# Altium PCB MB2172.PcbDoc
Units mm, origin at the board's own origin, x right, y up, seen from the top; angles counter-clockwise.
Board outline 55.25 x 31 mm, 2 copper layers (Top Layer, Bottom Layer), stack 0.603 mm thick; 40 components, 47 nets, 182 pads, 844 vias.
Unrouted connection lines stored in the file: 99.
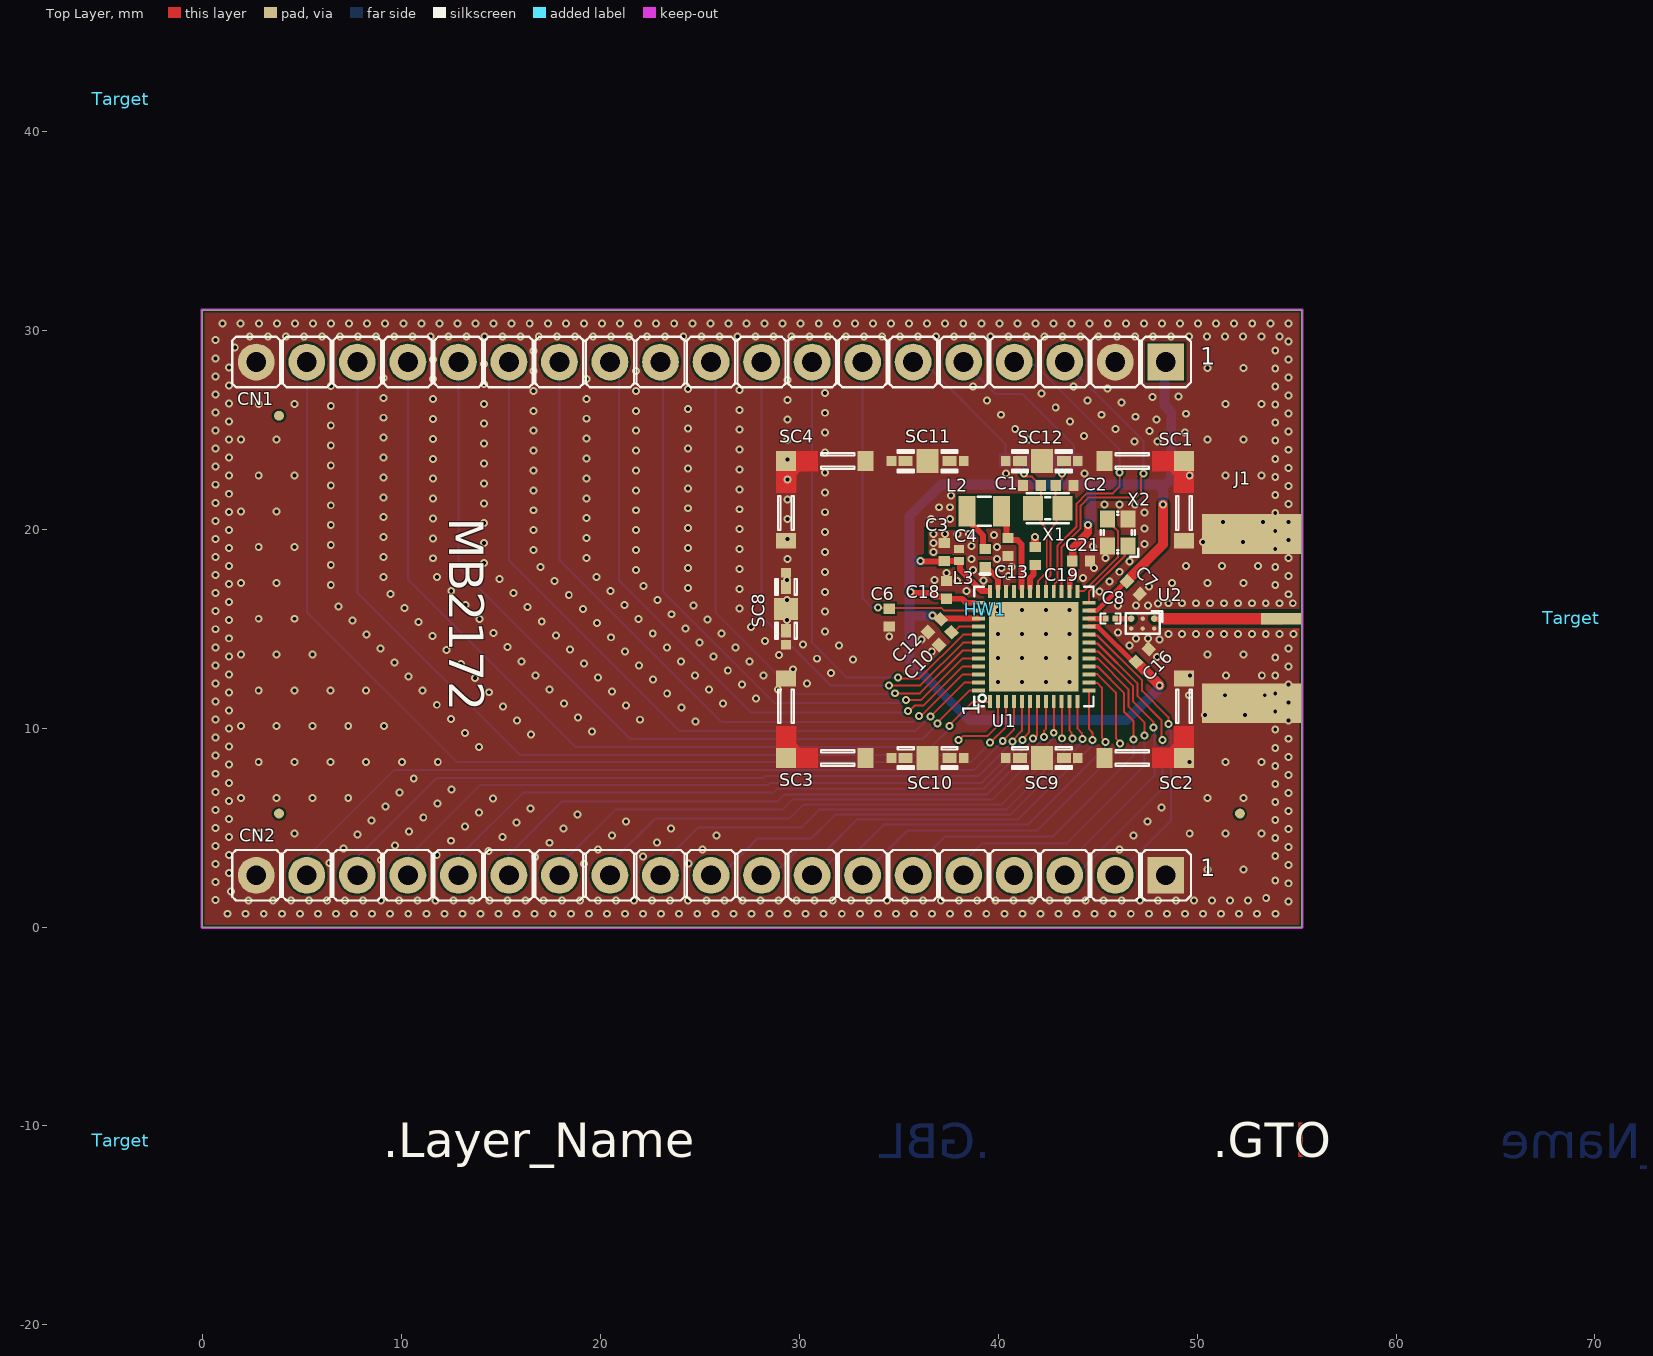
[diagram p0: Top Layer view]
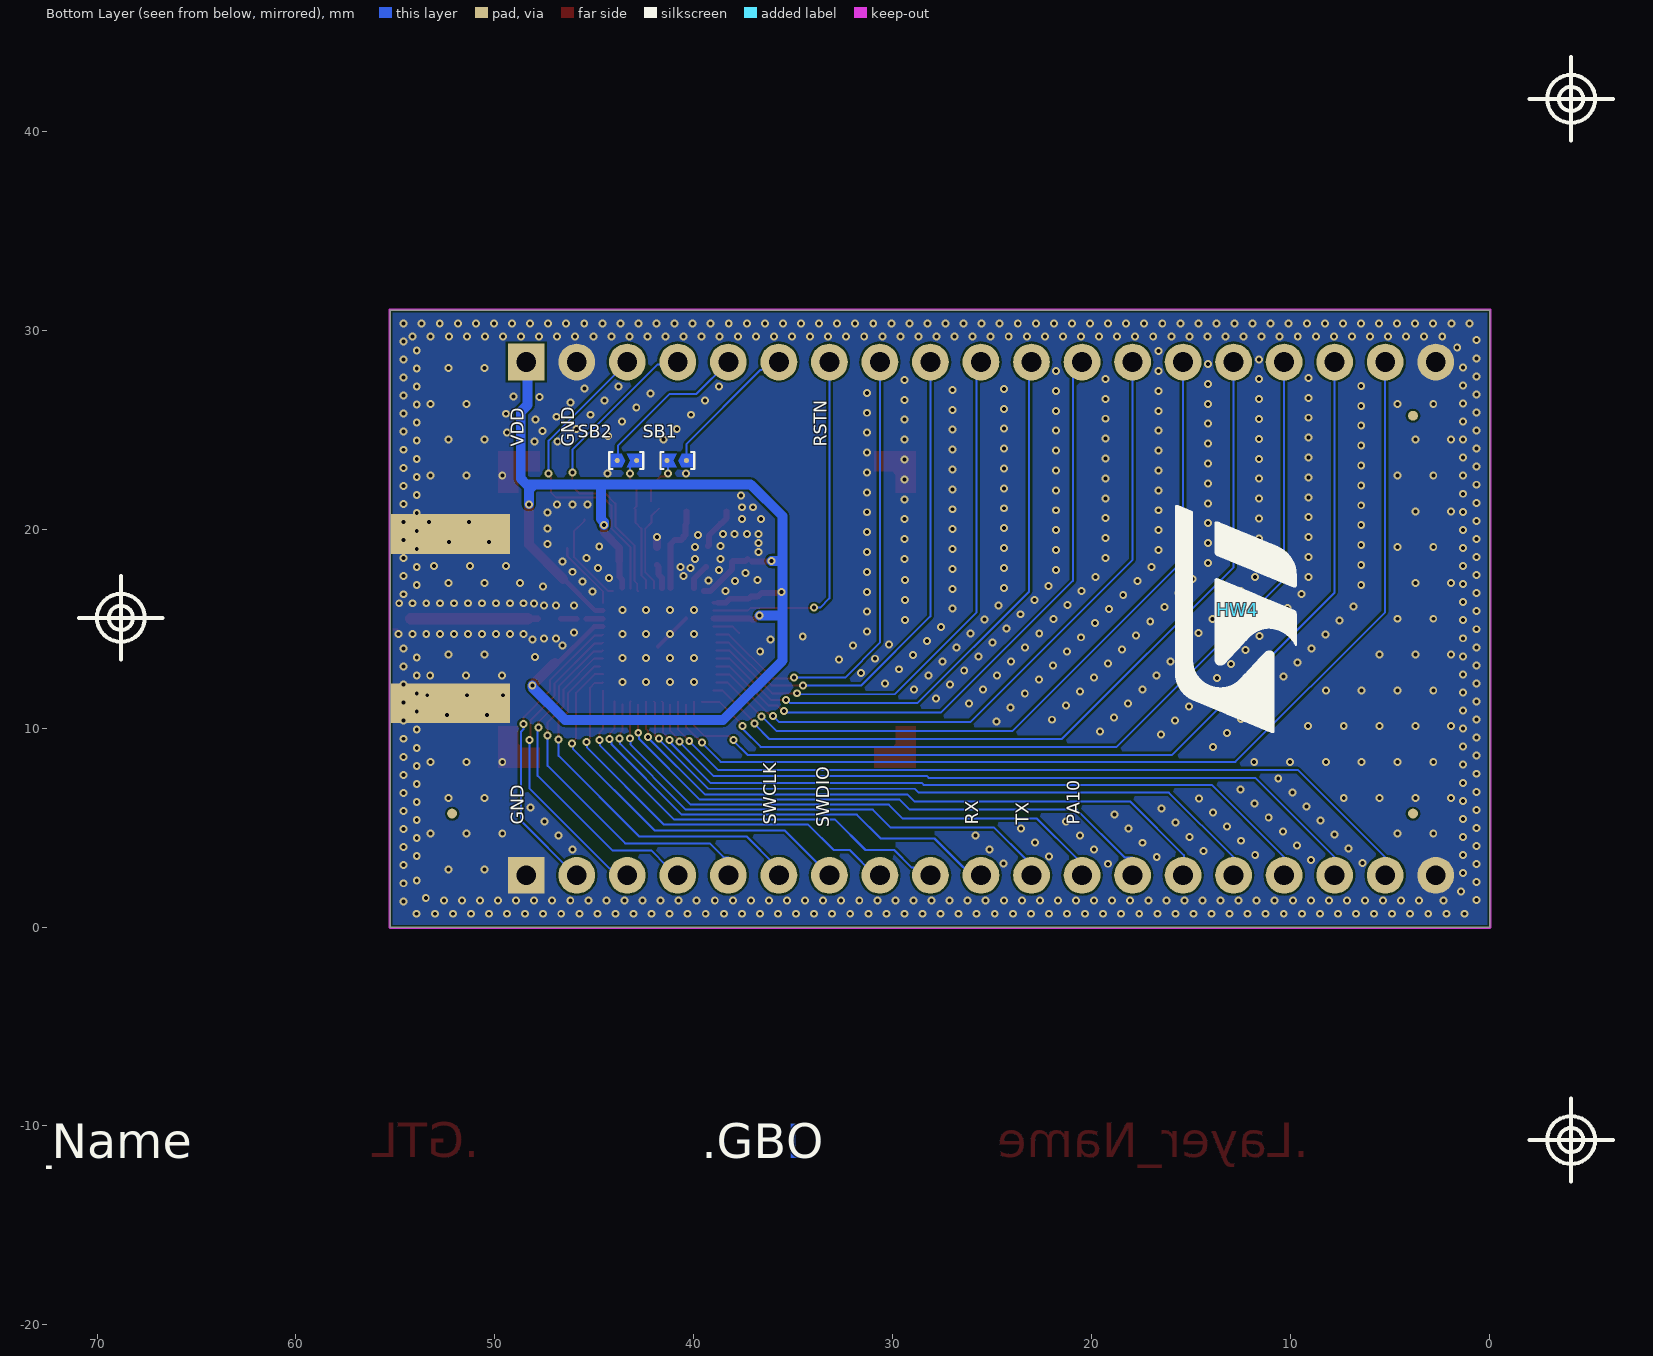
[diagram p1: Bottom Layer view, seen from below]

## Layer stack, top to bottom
Top Solder: solder mask 0.02, Solder Resist, Dk 3.5
Top Layer: signal copper 0.035
Dielectric 1: dielectric 0.533, TU-768 (3 x 7628), Dk 4.6
Bottom Layer: signal copper 0.035
Bottom Solder: solder mask 0.02, Solder Resist, Dk 3.5

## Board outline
0,0 55.25,0 55.25,31 0,31

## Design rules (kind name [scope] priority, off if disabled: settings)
Clearance Clearance_RF [InNet('NetJ1_1')] p1: gap=0.14 ignorepadtopadclearanceinfootprint=FALSE
Clearance [All] p2: gap=0.1 ignorepadtopadclearanceinfootprint=FALSE
HoleToHoleClearance [All] p1: gap=0.15 allowstackedmicrovias=TRUE
MinimumSolderMaskSliver [All] p1: minsoldermaskwidth=0
ParallelSegment [All] p1: limit=10 gap=0.3
PlaneClearance [All] p1: clearance=0
PlaneConnect [InNet('GND')] p1: planeconnectstyle=Direct reliefexpansion=0.508 reliefentries=4 reliefconductorwidth=0.254 reliefairgap=0.254
PolygonConnect [InNet('GND')] p1: connectstyle=Direct reliefconductorwidth=0.254 reliefentries=4 polygonreliefangle="90 Angle" airgapwidth=0.254
RoutingVias [All] p1: holewidth=0.2 width=0.4 viastyle="Through Hole" minholewidth=0.2 minwidth=0.4 maxholewidth=0.2 maxwidth=0.4
SilkToSilkClearance [All] p1: silktosilkclearance=0
SilkToSolderMaskClearance [IsPad] p1: minsilkscreentomaskgap=0 clearancetoexposedcopper=TRUE
SolderMaskExpansion [All] p1: expansion=0.102 istentingtop=FALSE
Width [All] p1: maxlimit=0.7 minlimit=0.1 preferedwidth=0.1
24 further rules are at their usual default settings.

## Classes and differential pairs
component class MB2172: C1 C2 C3 C4 C6 C7 C10 C12 C13 C16 C18 C19 C21 CN1 CN2 L2 L3 SB1 SB2 SC1 SC2 SC3 SC4 SC8 SC9 SC10 SC11 SC12 U1 U2 X1 X2

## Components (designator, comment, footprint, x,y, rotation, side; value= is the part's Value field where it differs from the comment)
C1 "Capacitor" C0402 41.691,22.2 r180 top value=10pF
C2 "Capacitor" C0402 43.341,22.2 r180 top value=10pF
C3 "Capacitor" C0402 37.291,18.85 r270 top value=4.7uF
C4 "Capacitor" C0201_H0P3 38.041,18.7 r270 top value=100nF
C6 "Capacitor" C0402 34.524,15.55 r270 top value=10nF
C7 "Capacitor" C0402 46.8,17.05 r135 top value=1uF
C8 "Capacitor" 20p_capacitor_SMD_0201 45.644,15.5 r90 top value=20pF
C10 "Capacitor" C0402 37.341,14.5 r225 top value=100nF
C12 "Capacitor" C0402 36.791,15.15 r45 top value=1uF
C13 "Capacitor" C0402 40.5,19.1 r90 top value=4.7uF
C16 "Capacitor" C0402 47.25,13.65 r225 top value=1uF
C18 "Capacitor" C0402 37.4,16.95 r270 top value=1uF
C19 "Capacitor" C0402 41.861,18.65 r270 top value=0.22uF
C21 "Capacitor" C0402 44.174,18.4 r180 top value=1uF
CN1 "Header 19x1" header_19x1 25.565,28.4 r180 top locked
CN2 "Header 19x1" header_19x1 25.565,2.6 r180 top locked
Designator16 "Comment" IMPEDANCE_TABLE 92.199,-23.657 r0 top
HW1 "S02-20150300" SHIELD_HARWIN_S02-20150300_15X20_H3 39.344,15.964 r90 top locked
HW4 "Logo" LOGO_ST 12.65,15.95 r90 bottom
J1 "SMA_connector" SMA_AMPHENOL_132415 54.225,15.5 r180 top
L2 "Inductor" IND_0805_MURATA_LQM21 39.299,20.9 r180 top value=10uH
L3 "Inductor" C0402 39.35,18.55 r270 top value=22nH
SB1 "SB_ON" SOLDER-BRIDGE_R0402-0R 40.823,23.45 r0 bottom value=0R
SB2 "SB_ON" SOLDER-BRIDGE_R0402-0R 43.4,23.45 r180 bottom value=0R
SC1 "Shield-clip_S0951-46R" CLIP_HARWIN_S0981-46R 49.337,23.418 r90 top value=S0981-46R
SC2 "Shield-clip_S0951-46R" CLIP_HARWIN_S0981-46R 49.337,8.5 r0 top value=S0981-46R
SC3 "Shield-clip_S0951-46R" CLIP_HARWIN_S0981-46R 29.337,8.5 r270 top locked value=S0981-46R
SC4 "Shield-clip_S0951-46R" CLIP_HARWIN_S0981-46R 29.337,23.418 r180 top value=S0981-46R
SC8 "Shield-clip_S0951-46R" CLIP_HARWIN_S0951-46R 29.337,15.993 r270 top value=S0951-46R
SC9 "Shield-clip_S0951-46R" CLIP_HARWIN_S0951-46R 42.198,8.5 r180 top value=S0951-46R
SC10 "Shield-clip_S0951-46R" CLIP_HARWIN_S0951-46R 36.448,8.5 r180 top value=S0951-46R
SC11 "Shield-clip_S0951-46R" CLIP_HARWIN_S0951-46R 36.448,23.418 r180 top value=S0951-46R
SC12 "Shield-clip_S0951-46R" CLIP_HARWIN_S0951-46R 42.198,23.418 r180 top value=S0951-46R
Target "" "Target PCB" -4.1,-10.71 r90 top
Target "" "Target PCB" 68.8,15.54 r90 top
Target "" "Target PCB" -4.1,41.628 r90 top
U1 "STM32WB07" ICC_QFN48-EPAD-4P5X4P5_6X6_P040 41.794,14.1 r90 top
U2 "MLPF-WB55-01E3" ICC_CSPG_6BUMPS_1X1P60_P050-P0577 47.265,15.25 r270 top value=MLPF-NRG-01D3
X1 "XTAL_2_PINS" CRY_NX2012SA_2P 42.491,21.05 r0 top value=32.768kHz
X2 "XTAL_4_PINS" CRY_NX2016SA_4P 46.011,19.831 r90 top value=32MHz

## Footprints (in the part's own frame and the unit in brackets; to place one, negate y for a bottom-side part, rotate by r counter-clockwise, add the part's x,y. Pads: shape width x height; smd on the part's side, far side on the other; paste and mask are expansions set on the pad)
20p_capacitor_SMD_0201 [mm] "SMD 0201"
  rect 0.3x0.28 smd mask+0.05: 1(0.002,0.238) 2(0.002,-0.232)
  silkscreen extent -0.25,-0.51 0.25,0.51, body extent -0.15,-0.3 0.15,0.3, height 0.3
C0201_H0P3 [mm] "MCD-00699"
  rect 0.4x0.5 smd mask+0.05: 1(-0.3,0) 2(0.3,0)
  body extent -0.32,-0.17 0.32,0.17, height 0.33
C0402 [mm]
  rect 0.51x0.56 smd mask+0.05: 1(-0.45,0) 2(0.45,0)
  body extent -0.5,-0.3 0.5,0.3, height 0.4
CLIP_HARWIN_S0951-46R [mm] "MCD-01587_CLIP-X1"
  rect 0.48x0.5 smd mask+0.1: 1(-1.81,0) 1(1.81,0)
  rect 0.7x0.5 smd mask+0.1: 1(-1.1,0) 1(1.1,0)
  rect 1.1x1.2 smd mask+0.1: 1(0,0)
  silkscreen extent -1.5,-0.55 1.5,0.55, body extent -2.05,-0.65 2.05,0.65, height 1.28
CLIP_HARWIN_S0981-46R [mm] "MCD-02164"
  rect 0.8x1 smd mask+0.05: 1(-4,0)
  rect 1x0.8 smd mask+0.05: 1(0,4)
  rect 1x1 smd mask+0.05: 1(0,0)
  Top Layer region: -1.6,-0.5 0.5,-0.5 0.5,1.6 -0.5,1.6 -0.5,0.7 -0.7,0.5 -1.6,0.5
  silkscreen extent -3.45,-0.4 0.4,3.45, body extent -4.3,-0.46 0.46,4.3, height 1.4
CRY_NX2012SA_2P [mm]
  rect 1x1.25 smd mask+0.05: 1(-0.75,0) 2(0.75,0)
  silkscreen extent -1.05,-0.75 1.05,0.75, body extent -1.05,-0.63 1.05,0.63, height 0.6
CRY_NX2016SA_4P [mm]
  rect 0.85x0.75 smd mask+0.05: 1(-0.675,-0.525) 2(0.675,-0.525) 3(0.675,0.525) 4(-0.675,0.525)
  silkscreen extent -1.22,-1.02 1.05,0.85, body extent -1.05,-0.85 1.05,0.85, height 0.7
header_19x1 [mm] "MCD-01897"
  rect 1.85x1.85 / inner round 1.85 / far side rect 1.85x1.85 hole 1 mask+0.05: 1(-22.86,0)
  round 1.85 hole 1 mask+0.05: 2(-20.32,0) 3(-17.78,0) 4(-15.24,0) 5(-12.7,0) 6(-10.16,0) 7(-7.62,0) 8(-5.08,0) 9(-2.54,0) 10(0,0) 11(2.54,0) 12(5.08,0) 13(7.62,0) 14(10.16,0) 15(12.7,0) 16(15.24,0) 17(17.78,0) 18(20.32,0) 19(22.86,0)
  silkscreen extent -24.13,-1.27 24.07,1.27, body extent -24.26,-1.27 21.59,1.27, height 8.38
ICC_CSPG_6BUMPS_1X1P60_P050-P0577 [mm] "MCD-03490"
  round 0.32 smd paste+0 mask+0: A1(-0.25,0.577) A3(-0.25,-0.577)
  round 0.22 smd paste+0 mask+0: A2(-0.25,0) B1(0.25,0.577) B2(0.25,0) B3(0.25,-0.577)
  silkscreen extent -0.64,-0.85 0.51,0.97, body extent -0.51,-0.81 0.51,0.81, height 0.7
ICC_QFN48-EPAD-4P5X4P5_6X6_P040 [mm] "MCD-03488"
  rect 0.65x0.2 smd mask+0.05: 1(-2.775,2.2) 2(-2.775,1.8) 3(-2.775,1.4) 4(-2.775,1) 5(-2.775,0.6) 6(-2.775,0.2) 7(-2.775,-0.2) 8(-2.775,-0.6) 9(-2.775,-1) 10(-2.775,-1.4) 11(-2.775,-1.8) 12(-2.775,-2.2) 25(2.775,-2.2) 26(2.775,-1.8) 27(2.775,-1.4) 28(2.775,-1) 29(2.775,-0.6) 30(2.775,-0.2) 31(2.775,0.2) 32(2.775,0.6) 33(2.775,1) 34(2.775,1.4) 35(2.775,1.8) 36(2.775,2.2)
  rect 0.2x0.65 smd mask+0.05: 13(-2.2,-2.775) 14(-1.8,-2.775) 15(-1.4,-2.775) 16(-1,-2.775) 17(-0.6,-2.775) 18(-0.2,-2.775) 19(0.2,-2.775) 20(0.6,-2.775) 21(1,-2.775) 22(1.4,-2.775) 23(1.8,-2.775) 24(2.2,-2.775) 37(2.2,2.775) 38(1.8,2.775) 39(1.4,2.775) 40(1,2.775) 41(0.6,2.775) 42(0.2,2.775) 43(-0.2,2.775) 44(-0.6,2.775) 45(-1,2.775) 46(-1.4,2.775) 47(-1.8,2.775) 48(-2.2,2.775)
  rect 4.5x4.5 smd mask+0.05: 49(0,0)
  silkscreen extent -3,-3 3,3, body extent -3,-3 3,3, height 0.91
IMPEDANCE_TABLE [mm]
IND_0805_MURATA_LQM21 [mm] "MCD-02317"
  rect 0.85x1.55 smd mask+0.05: 1(-0.875,0) 2(0.875,0)
  silkscreen extent -0.33,-0.72 0.33,0.72, body extent -1.1,-0.72 1.1,0.72, height 1.45
LOGO_ST [mm]
  silkscreen extent -6.18,-2.95 5.25,3.14
SHIELD_HARWIN_S02-20150300_15X20_H3 [mm] "MCD-03126"
  body extent -7.6,-10.1 7.6,10.1, height 3.25
SMA_AMPHENOL_132415 [mm]
  rect 2.05x0.58 smd mask+0: 1(0,0)
  rect 5x2 smd: 2(1.475,4.25) 2(1.475,-4.25)
  rect 6x2 smd far side: 2(1.975,4.25) 2(1.975,-4.25)
  body extent -10.55,-4.76 4.36,4.76, height 4.11
SOLDER-BRIDGE_R0402-0R [mil] "MCD-01619"
  round 10 smd paste-393.7: 1(-17.72,0) 2(20.67,0)
  Top Layer region: -30.51,-13.78 -30.51,13.78 -8.37,13.78 -1.48,0 -8.37,-13.78
  Top Layer region: 1.48,13.78 8.37,0 1.48,-13.78 30.51,-13.78 30.51,13.78
  silkscreen extent -33,-17 33,17, body extent -20,-12 20,12, height 14
"Target PCB" [mm] "TargetA"

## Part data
C1 C2: library part MCD-00015, "Capacitor, MLCC, 10pF, 50V, NPO, +/-5%, 0402, T=0.5mm", Manufacturer=YAGEO, Manufacturer_Part_Number=CC0402JRNPO9BN100, Package=0402
C3 C13: library part MCD-03431, "Capacitor, MLCC, 4.7uF, X5R, 10V, +/-20%, 0402, T=0.5mm", Manufacturer=MURATA, Manufacturer_Part_Number=GRM155R61A475MEAAD, Package=0402
C4: library part MCD-01535, "Capacitor, MLCC,100nF, 10V, X5R, +/-10%, 0201, T=0.3mm", Manufacturer=MURATA, Manufacturer_Part_Number=GRM033R61A104KE15, Package=0201
C6: library part MCD-00011, "Capacitor, MLCC, 10nF, 16V, X7R, +/-10%, 0402, T=0.5mm", Manufacturer=YAGEO, Manufacturer_Part_Number=CC0402KRX7R7BB103, Package=0402
C7 C12 C16 C18 C21: library part MCD-03432, "Capacitor, MLCC, 1uF, X7R, 6.3V,+/- 10%, 0402, T=0.5mm", Manufacturer=MURATA, Manufacturer_Part_Number=GRM155R70J105KA12, Package=0402
C8: library part MCD-03543, "Capacitor, MLCC, 20pF, 25V, COG, +/-2%, 0201, T=0.3mm", Manufacturer=MURATA, Manufacturer_Part_Number=GJM0335C1E200GB01, Package=0201
C10: library part MCD-02355, "Capacitor, MLCC, 100nF, 25V, X7R, +/-10%, 0402, T=0.5mm", Manufacturer=WALSIN, Manufacturer_Part_Number=0402B104K250CT, Package=0402
C19: library part MCD-03483, "Capacitor, MLCC, 0.22uF, X5R, 6.3V, +/-10%, 0402, T=0.5mm", Manufacturer=YAGEO, Manufacturer_Part_Number=CC0402KRX5R5BB224, Package=0402
CN1 CN2: library part HEADER_19X1, "Header, 18x1, 2.54mm, VR, TH, T=5.84mm/8.38mm", Manufacturer=SAMTEC, Manufacturer_Part_Number=TSW-118-07-L-S, Package=TSW
Designator16: library part MCD-00279
HW1: library part MCD-03126, "RFI shield can, 20x15x3mm", Manufacturer=HARWIN, Package=20x15x3mm
HW4: library part MCD-00625, "\"STMicroelectronics\" logo footprint for PCB"
J1: "Rf Connector, Sma End Launch Recept Jack For .032\" Pcb / Individual Bag", Manufacturer="Amphenol Connex", Manufacturer Part Number=132415, Supplier Part Number 1=132415-ND
L2: library part MCD-03438, "Inductor, MLCC, 10uH, +/-20%, 300mA, 845mR, 0805, T=1.45mm", Manufacturer=MURATA, Manufacturer_Part_Number=LQM21DN100M70L, Package=0805
L3: library part MCD-03439, "Inductor, MLCC, 22nH, +/-2%, 350mA, 0.58R, 0402, T=1.45mm", Manufacturer=MURATA, Manufacturer_Part_Number=LQG15HN22NG02D, Package=0402
SB1 SB2: library part MCD-01618, "Resistor, 0R, SB0402, 5%, 0.063W", Manufacturer=YAGEO, Manufacturer_Part_Number=RC0402JR-070RL, Package=0402
SC1 SC2 SC3 SC4: library part MCD-02164, "Shield clip Harwin S0981-46R to fix RF shielded cavity", Manufacturer=HARWIN, Manufacturer_Part_Number=S0981-46R, Package=0.8x4.7x1.4mm
SC8 SC9 SC10 SC11 SC12: library part MCD-01587, "RFI shield clip mini TIN SMD", Manufacturer=HARWIN, Manufacturer_Part_Number=S0951-46R, Package=1.1x3.9mm
U1: library part MCD-03836, "IC, Bluetooth Low Energy wireless SoC, QFN48", Manufacturer=STMICROELECTRONICS, Manufacturer_Part_Number=STM32WB07CCV6UTR, Package=QFN48
U2: library part MCD-03490, "2.4 GHz low pass filter matched to BLUENRG-LP-LPS", Manufacturer=STMICROELECTRONICS, Manufacturer_Part_Number=MLPF-NRG-01D3, Package=CSP
X1: library part MCD-01445, "Crystal, 32.768kHz, 7pF, +/-20ppm, 80K, 2.05x1.2mm", Manufacturer=NDK, Manufacturer_Part_Number=NX2012SA-32.768KHZ-EXS00A-MU00389, Package=2.05x1.2mm
X2: library part MCD-01446, "Crystal, 32MHz, 8pF, +/-10ppm, 60R, 2x1.6mm", Manufacturer=NDK, Manufacturer_Part_Number=NX2016SA-32MHZ-EXS00A-CS06654, Package=2x1.6mm

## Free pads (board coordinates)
  round 0.5 all layers, no hole mask+0: 1(3.85,5.7) 1(3.85,25.7) 1(52.15,5.7)
  round 0.508 on Mech16: 1(20.768,-18.512) 1(69.616,-18.512)

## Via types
v1: diameter 0.4, hole 0.2, Top Layer to Bottom Layer, tented both sides, 844 vias

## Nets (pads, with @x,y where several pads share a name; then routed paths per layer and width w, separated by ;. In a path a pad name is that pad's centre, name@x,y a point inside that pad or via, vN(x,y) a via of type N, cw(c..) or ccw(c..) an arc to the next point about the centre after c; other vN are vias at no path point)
GND: C1.2 C2.1 C3.1 C4.1 C6.2 C7.1 C10.2 C12.1 C13.1 C16.1 C18.1 C19.1 C21.1 CN1.2 CN1.19 CN2.1 CN2.19 J1.2 SC1.1 SC2.1 SC3.1 SC4.1 SC8.1 SC9.1 SC10.1 SC11.1 SC12.1 U1.34 U1.49 U2.A2 U2.B1 U2.B2 U2.B3 X2.2 X2.4 | length 2.5
  Top Layer w0.2: U1.49@40.394,15.5 U1.49
  Top Layer w0.4: v1(41.85,19.6) 41.85,19.111 C19.1
  other v1: 1.265,0.666 2.173,0.666 3.081,0.666 3.989,0.666 4.897,0.666 5.805,0.666 6.713,0.666 7.621,0.666 8.529,0.666 9.437,0.666 10.345,0.666 11.253,0.666 12.161,0.666 13.069,0.666 13.977,0.666 14.885,0.666 15.793,0.666 16.701,0.666 17.609,0.666 18.517,0.666 19.425,0.666 20.333,0.666 21.241,0.666 22.149,0.666 23.057,0.666 23.965,0.666 24.873,0.666 25.781,0.666 26.689,0.666 27.597,0.666 28.505,0.666 29.413,0.666 30.321,0.666 31.229,0.666 32.137,0.666 33.045,0.666 33.953,0.666 34.861,0.666 35.769,0.666 36.677,0.666 37.585,0.666 38.493,0.666 39.401,0.666 40.309,0.666 41.217,0.666 42.125,0.666 43.033,0.666 43.941,0.666 44.849,0.666 45.757,0.666 46.665,0.666 47.573,0.666 48.481,0.666 49.389,0.666 50.297,0.666 51.205,0.666 52.113,0.666 53.021,0.666 53.929,0.666 54.588,1.291 2.322,1.326 3.535,1.326 4.443,1.326 5.351,1.326 6.259,1.326 7.167,1.326 8.075,1.326 8.983,1.326 9.891,1.326 10.799,1.326 11.707,1.326 12.615,1.326 13.523,1.326 14.431,1.326 15.339,1.326 16.247,1.326 17.155,1.326 18.063,1.326 18.971,1.326 19.879,1.326 20.787,1.326 21.695,1.326 22.603,1.326 23.511,1.326 24.419,1.326 25.327,1.326 26.235,1.326 27.143,1.326 28.051,1.326 28.959,1.326 29.867,1.326 30.775,1.326 31.683,1.326 32.591,1.326 33.499,1.326 34.407,1.326 35.315,1.326 36.223,1.326 37.131,1.326 38.039,1.326 38.947,1.326 39.855,1.326 40.763,1.326 41.671,1.326 42.579,1.326 43.487,1.326 44.395,1.326 45.303,1.326 46.211,1.326 47.119,1.326 48.027,1.326 48.935,1.326 49.843,1.326 50.751,1.326 51.659,1.326 52.567,1.326 0.666,1.348 53.474,1.45 1.445,1.791 54.588,2.199 0.666,2.256 53.928,2.34 1.326,2.71 50.529,2.895 52.329,2.895 54.588,3.107 0.666,3.164 19.179,3.179 24.436,3.186 6.379,3.229 8.979,3.379 16.729,3.529 22.136,3.536 53.928,3.561 1.326,3.618 11.779,3.629 14.379,3.829 19.886,3.886 25.143,3.893 46.093,3.893 7.086,3.936 54.588,4.015 0.666,4.072 9.686,4.086 17.436,4.236 22.843,4.243 12.486,4.336 53.928,4.469 1.326,4.526 15.086,4.536 20.593,4.593 25.85,4.6 46.8,4.6 7.793,4.643 2.829,4.695 4.629,4.695 49.629,4.695 51.429,4.695 53.229,4.695 10.393,4.793 54.588,4.923 18.143,4.943 23.55,4.95 0.666,4.98 13.193,5.043 15.793,5.243 21.3,5.3 47.507,5.307 8.5,5.35 53.928,5.377 1.326,5.434 11.1,5.5 18.85,5.65 13.9,5.75 54.588,5.831 0.666,5.888 16.5,5.95 48.214,6.014 9.207,6.057 11.807,6.207 53.928,6.285 1.326,6.342 14.607,6.457 1.929,6.495 3.729,6.495 5.529,6.495 7.329,6.495 50.529,6.495 52.329,6.495 54.588,6.739 9.914,6.764 0.666,6.796 12.514,6.914 53.928,7.193 1.326,7.25 10.621,7.471 54.588,7.647 0.666,7.704 53.928,8.101 1.326,8.158 2.829,8.295 4.629,8.295 6.429,8.295 8.229,8.295 10.029,8.295 11.829,8.295 49.629,8.295 51.429,8.295 53.229,8.295 54.588,8.555 0.666,8.612 53.928,9.009 1.326,9.066 13.9,9.05 54.588,9.463 0.666,9.52 16.521,9.679 13.193,9.757 19.578,9.822 53.928,9.917 1.326,9.974 1.929,10.095 3.729,10.095 5.529,10.095 7.329,10.095 9.129,10.095 24.778,10.322 15.814,10.386 54.588,10.371 22.006,10.419 0.666,10.428 12.486,10.464 18.871,10.529 50.4,10.65 52.4,10.65 53.928,10.825 1.326,10.882 24.071,11.029 15.107,11.093 21.299,11.126 11.779,11.171 26.171,11.229 18.164,11.236 54.588,11.279 0.666,11.336 27.821,11.479 49.6,11.65 51.4,11.65 53.4,11.65 23.364,11.736 53.928,11.733 1.326,11.79 14.4,11.8 20.592,11.833 11.072,11.878 2.829,11.895 4.629,11.895 6.429,11.895 8.229,11.895 17.457,11.943 25.464,11.936 28.921,11.929 27.114,12.186 54.588,12.187 0.666,12.244 30.4,12.25 39.996,12.325 41.196,12.325 42.396,12.325 43.596,12.325 22.657,12.443 13.693,12.507 19.885,12.54 10.364,12.586 16.75,12.65 24.757,12.643 28.214,12.636 49.65,12.65 51.45,12.65 53.25,12.65 53.928,12.641 1.326,12.698 31.601,12.778 26.407,12.893 29.693,12.957 54.588,13.095 0.666,13.152 21.95,13.15 12.986,13.214 19.178,13.247 9.657,13.293 16.043,13.357 24.05,13.35 27.507,13.343 32.701,13.436 30.894,13.485 39.996,13.525 41.196,13.525 42.396,13.525 43.596,13.525 47.977,13.569 53.928,13.549 1.326,13.606 25.7,13.6 28.986,13.664 1.929,13.695 3.729,13.695 5.529,13.695 50.529,13.695 52.329,13.695 36.661,13.85 21.243,13.857 12.278,13.922 18.471,13.954 8.95,14 54.588,14.003 26.8,14.05 0.666,14.06 15.336,14.064 23.343,14.057 31.994,14.143 46.6,14.15 30.187,14.192 24.993,14.307 28.279,14.371 36.15,14.45 48.1,14.45 46.928,14.5 47.528,14.5 1.326,14.514 20.536,14.564 34.524,14.6 11.571,14.629 17.763,14.662 8.243,14.707 39.996,14.725 41.196,14.725 42.396,14.725 43.596,14.725 48.55,14.725 49.25,14.725 49.95,14.725 50.65,14.725 51.35,14.725 52.05,14.725 52.75,14.725 53.45,14.725 54.15,14.731 54.85,14.737 22.636,14.764 26.093,14.757 14.628,14.772 46.028,14.795 31.287,14.85 0.666,14.968 24.286,15.014 27.572,15.078 19.828,15.272 10.864,15.336 17.056,15.369 1.326,15.422 7.536,15.414 29.384,15.443 21.928,15.472 25.386,15.464 2.829,15.495 4.629,15.495 13.921,15.479 23.578,15.722 31.287,15.85 0.666,15.876 39.996,15.925 41.196,15.925 42.396,15.925 43.596,15.925 19.121,15.979 27,16 10.157,16.043 16.349,16.076 6.829,16.121 46.028,16.15 46.928,16.15 47.528,16.15 13.214,16.186 21.221,16.179 24.678,16.172 48.023,16.259 48.55,16.275 49.25,16.275 49.95,16.275 50.65,16.275 51.35,16.275 52.05,16.275 52.75,16.275 53.45,16.275 54.15,16.275 54.808,16.275 1.326,16.33 22.871,16.429 29.384,16.443 18.414,16.686 54.588,16.727 9.45,16.75 0.666,16.784 15.642,16.783 31.287,16.85 12.507,16.893 20.514,16.886 45.086,16.876 38.4,16.9 27,17 24.4,17.05 47.577,17.119 22.164,17.136 6.45,17.2 53.928,17.181 1.326,17.238 1.929,17.295 3.729,17.295 48.729,17.295 50.529,17.295 52.329,17.295 45.586,17.376 17.707,17.393 37.932,17.382 39.264,17.423 29.384,17.443 36.8,17.45 14.935,17.49 44.273,17.55 9.1,17.6 11.8,17.6 19.807,17.593 54.588,17.635 40.515,17.65 0.666,17.692 37.4,17.8 31.287,17.85 46.108,17.857 21.8,17.95 38.744,17.942 27,18 24.4,18.05 40.161,18.05 44.824,18.05 53.928,18.089 17,18.1 40.661,18.1 1.326,18.146 49.45,18.15 51.25,18.15 53.05,18.15 6.45,18.2 14.15,18.3 46.608,18.384 29.4,18.5 38.65,18.5 39.941,18.5 11.595,18.537 54.588,18.543 19.3,18.55 45.392,18.557 0.666,18.6 9.1,18.6 31.287,18.85 36.741,18.85 16.65,18.95 21.8,18.95 27,19 53.928,18.997 1.326,19.054 24.4,19.05 2.829,19.095 4.629,19.095 39.941,19.1 38.65,19.15 44.754,19.138 6.45,19.2 47.361,19.25 14.15,19.3 36.741,19.3 50.3,19.35 52.3,19.35 54.588,19.451 0.666,19.508 29.4,19.5 11.595,19.537 19.3,19.55 9.1,19.6 39.8,19.7 36.741,19.75 37.315,19.75 37.965,19.75 38.524,19.75 31.287,19.85 53.928,19.905 1.326,19.962 16.65,19.95 21.8,19.95 27,20 47.361,20.034 24.4,20.05 6.45,20.2 14.15,20.3 51.3,20.35 53.3,20.35 54.588,20.359 0.666,20.416 29.4,20.5 36.624,20.5 37.574,20.5 11.595,20.537 19.3,20.55 9.1,20.6 47.361,20.828 53.928,20.813 31.287,20.85 1.326,20.87 1.929,20.895 3.729,20.895 16.65,20.95 21.8,20.95 27,21 24.4,21.05 37.024,21.1 37.574,21.1 6.45,21.2 45.35,21.25 46.096,21.25 46.889,21.25 54.588,21.267 14.15,21.3 0.666,21.324 29.4,21.5 11.595,21.537 19.3,21.55 9.1,21.6 37.624,21.7 53.928,21.721 1.326,21.778 31.287,21.85 16.65,21.95 21.8,21.95 27,22 24.4,22.05 54.588,22.175 6.45,22.2 0.666,22.232 14.15,22.3 29.4,22.5 11.595,22.537 19.3,22.55 9.1,22.6 53.928,22.629 1.326,22.686 2.829,22.695 4.629,22.695 49.629,22.695 51.429,22.695 53.229,22.695 40.4,22.8 44.35,22.8 31.287,22.85 16.65,22.95 21.8,22.95 27,23 24.4,23.05 54.588,23.083 0.666,23.14 6.45,23.2 14.15,23.3 29.4,23.5 11.595,23.537 19.3,23.55 53.928,23.537 1.326,23.594 9.1,23.6 31.287,23.85 16.65,23.95 21.8,23.95 27,24 54.588,23.991 0.666,24.048 24.4,24.05 6.45,24.2 14.15,24.3 46.842,24.408 48,24.4 53.928,24.445 1.326,24.502 1.929,24.495 3.729,24.495 29.4,24.5 41.529,24.495 50.529,24.495 52.329,24.495 11.595,24.537 19.3,24.55 9.1,24.6 44.307,24.693 31.287,24.85 49.4,24.85 54.588,24.899 16.65,24.95 21.8,24.95 47.607,24.943 0.666,24.956 27,25 24.4,25.05 40.857,25.043 45.907,25.043 6.45,25.2 14.15,25.3 53.928,25.353 43.6,25.4 1.326,25.41 29.4,25.5 47.95,25.5 11.595,25.537 19.3,25.55 9.1,25.6 46.9,25.65 40.15,25.75 45.2,25.75 49.45,25.8 54.588,25.807 0.666,25.864 31.287,25.85 16.65,25.95 21.8,25.95 27,26 24.4,26.05 42.893,26.107 6.45,26.2 53.928,26.261 2.829,26.295 4.629,26.295 51.429,26.295 53.229,26.295 1.326,26.318 14.15,26.3 46.193,26.357 39.443,26.457 44.493,26.457 29.4,26.5 11.595,26.537 19.3,26.55 9.1,26.6 47.75,26.65 49.061,26.678 54.588,26.715 0.666,26.772 42.186,26.814 31.287,26.85 16.65,26.95 21.8,26.95 27,27 24.4,27.05 45.486,27.064 38.736,27.164 43.786,27.164 53.928,27.169 6.45,27.2 1.326,27.226 14.15,27.3 29.4,27.5 11.595,27.537 19.3,27.55 9.1,27.6 54.588,27.623 0.666,27.68 16.65,27.95 21.8,27.95 50.529,28.095 52.329,28.095 53.928,28.077 1.326,28.134 14.15,28.3 54.588,28.531 11.595,28.537 0.666,28.588 16.65,28.95 53.928,28.985 1.625,29.131 54.588,29.439 0.666,29.496 2.378,29.674 3.286,29.674 4.194,29.674 5.102,29.674 6.01,29.674 6.918,29.674 7.826,29.674 8.734,29.674 9.642,29.674 10.55,29.674 11.458,29.674 12.366,29.674 13.274,29.674 14.182,29.674 15.09,29.674 15.998,29.674 16.906,29.674 17.814,29.674 18.722,29.674 19.63,29.674 20.538,29.674 21.446,29.674 22.354,29.674 23.262,29.674 24.17,29.674 25.078,29.674 25.986,29.674 26.894,29.674 27.802,29.674 28.71,29.674 29.618,29.674 30.526,29.674 31.434,29.674 32.342,29.674 33.25,29.674 34.158,29.674 35.066,29.674 35.974,29.674 36.882,29.674 37.79,29.674 38.698,29.674 39.606,29.674 40.514,29.674 41.422,29.674 42.33,29.674 43.238,29.674 44.146,29.674 45.054,29.674 45.962,29.674 46.87,29.674 47.778,29.674 48.686,29.674 49.594,29.674 50.502,29.674 51.41,29.674 52.318,29.674 53.226,29.674 54.134,29.674 1.016,30.334 1.924,30.334 2.832,30.334 3.74,30.334 4.648,30.334 5.556,30.334 6.464,30.334 7.372,30.334 8.28,30.334 9.188,30.334 10.096,30.334 11.004,30.334 11.912,30.334 12.82,30.334 13.728,30.334 14.636,30.334 15.544,30.334 16.452,30.334 17.36,30.334 18.268,30.334 19.176,30.334 20.084,30.334 20.992,30.334 21.9,30.334 22.808,30.334 23.716,30.334 24.624,30.334 25.532,30.334 26.44,30.334 27.348,30.334 28.256,30.334 29.164,30.334 30.072,30.334 30.98,30.334 31.888,30.334 32.796,30.334 33.704,30.334 34.612,30.334 35.52,30.334 36.428,30.334 37.336,30.334 38.244,30.334 39.152,30.334 40.06,30.334 40.968,30.334 41.876,30.334 42.784,30.334 43.692,30.334 44.6,30.334 45.508,30.334 46.416,30.334 47.324,30.334 48.232,30.334 49.14,30.334 50.048,30.334 50.956,30.334 51.864,30.334 52.772,30.334 53.68,30.334 54.588,30.334
NetC1_1: C1.1 SB1.2 U1.30 X1.1 | length 7.1
  Top Layer w0.1: v1(41.3,22.8) 41.3,22.75 41.407,22.643 41.698,22.643 C1.1 ; X1.1 42.127,20.664 42.127,20.334 42.441,20.02 42.441,17.83 41.994,17.382 U1.30@41.994,17.025 ; C1.1@42.092,22.149 C1.1@42.141,22.1 ; X1.1@42.141,21.4 C1.1@42.141,22.075
  Bottom Layer w0.1: SB1.2@41.238,23.493 41.3,23.431 v1(41.3,22.8)
NetC2_2: C2.2 SB2.2 U1.29 X1.2 | length 6.9
  Top Layer w0.1: U1.29@42.394,17.025 42.394,17.433 42.641,17.68 42.641,20.03 42.925,20.314 42.925,20.984 42.991,21.05 42.891,21.15 42.891,22.1 42.891,22.225 43.096,22.43 43.121,22.43 43.2,22.509 v1@43.2,22.798
  Bottom Layer w0.1: SB2.2@42.968,23.379 43.2,23.147 v1(43.2,22.8)
NetC8_1: C8.1 U1.22 | length 0.8
  Top Layer w0.28: U1.22 C8.1@45.405,15.5
NetC8_2: C8.2 U2.A3 | length 0.8
  Top Layer w0.28: C8.2@45.875,15.5 U2.A3
NetC10_1: C10.1 U1.40 | length 1.4
  Top Layer w0.1: C10.1@37.709,14.768 38.041,15.1 U1.40
NetC13_2: C13.2 L2.1 U1.32 | length 4.4
  Top Layer w0.3: L2.1@40.366,20.9 40.366,20.283 40.424,20.225 40.424,19.7 C13.2@40.524,19.6 ; C13.2@40.524,19.65 40.524,19.553 40.63,19.447 40.968,19.447 41.174,19.241 U1.32@41.174,17.05
NetC19_2: C19.2 U1.31 | length 1.3
  Top Layer w0.3: U1.31@41.594,17.05 41.594,17.532 41.775,17.714 41.775,18.114 C19.2
NetJ1_1: J1.1 U2.A1 | length 6.4
  Top Layer w0.32: U2.A1 48.35,15.5
  Top Layer w0.58: 48.35,15.5 J1.1
NetL2_2: L2.2 L3.1 | length 2.2
  Top Layer w0.3: L2.2@38.349,20.9 38.349,20.55 38.624,20.275 38.649,20.275 39.247,19.677 39.247,19.194 L3.1@39.291,19.15
NetL3_2: L3.2 U1.35 | length 1.3
  Top Layer w0.3: L3.2@39.399,18.099 39.994,17.504 U1.35@39.994,17.05
NetU1_24: U1.24 X2.1 | length 3.5
  Top Layer w0.105: U1.24 44.561,16.307 44.561,16.85 46.361,18.65 X2.1@46.361,19.05
NetU1_25: U1.25 X2.3 | length 4.8
  Top Layer w0.1: U1.25@44.052,16.9 44.325,16.9 46.011,18.586 46.011,19.911 45.822,20.1 45.811,20.1 45.486,20.425 X2.3@45.486,20.475
PA0: CN2.9 U1.13 | length 22.2
  Top Layer w0.1: U1.13 44.569,9.942 44.741,9.77 v1(44.741,9.4)
  Bottom Layer w0.1: CN2.9 28.579,2.6 28.966,2.988 29.038,2.988 29.92,3.87 31.37,3.87 32.9,5.4 40.992,5.4 44.719,9.127 44.719,9.378 v1(44.741,9.4)
PA1: CN2.8 U1.14 | length 21.2
  Top Layer w0.1: U1.14 44.601,12.268 44.973,12.268 45.211,12.03 45.211,9.509 45.391,9.329 v1@45.391,9.3
  Bottom Layer w0.1: CN2.8 30.9,2.6 32.17,3.87 32.97,3.87 34.25,5.15 41.5,5.15 45.378,9.028 45.378,9.278 v1(45.4,9.3)
PA2: CN2.7 U1.15 | length 20.1
  Top Layer w0.1: U1.15 44.575,12.706 44.985,12.706 45.911,11.78 45.911,9.484 46.132,9.262 v1@46.132,9.225
  Bottom Layer w0.1: CN2.7@33.262,2.689 35.424,4.85 41.962,4.85 46.079,8.967 46.079,9.172 v1(46.124,9.217)
PA3: CN2.6 U1.16 | length 18.7
  Top Layer w0.1: U1.16@44.719,13.1 44.991,13.1 46.332,11.759 46.332,10.809 46.811,10.33 v1(46.811,9.422)
  Bottom Layer w0.1: CN2.6@35.908,3.107 37.35,4.55 42.75,4.55 46.8,8.6 v1@46.8,9.454
PA4: CN2.5 U1.17 | length 17.8
  Top Layer w0.1: U1.17 44.996,13.5 46.561,11.935 46.561,11.08 47.363,10.278 v1(47.363,9.617)
  Bottom Layer w0.1: CN2.5@38.265,3.5 38.5,3.5 39.2,4.2 43.45,4.2 47.35,8.1 47.35,9.55 v1@47.4,9.6
PA5: CN2.4 U1.18 | length 16.3
  Top Layer w0.1: U1.18 44.619,13.85 45.041,13.85 46.786,12.105 46.786,11.325 47.797,10.314 47.797,10.028 v1(47.8,10.026)
  Bottom Layer w0.1: CN2.4@41.356,3.056 42.15,3.85 44.1,3.85 47.85,7.6 47.85,9.976 v1(47.8,10.026)
PA6: CN2.3 U1.19 | length 15.8
  Top Layer w0.1: U1.19 44.619,14.25 44.991,14.25 47.011,12.23 47.011,11.6 48.209,10.402 48.209,9.441 v1(48.25,9.4)
  Bottom Layer w0.1: CN2.3 43.68,2.935 44.235,2.935 48.25,6.95 v1(48.25,9.4)
PA7: CN2.2 U1.20 | length 15.2
  Top Layer w0.1: U1.20 44.619,14.65 44.991,14.65 47.241,12.4 47.241,11.87 48.559,10.552 v1(48.559,10.214)
  Bottom Layer w0.1: CN2.2 45.95,2.6 48.687,5.337 48.687,9.813 48.57,9.93 48.57,10.203 v1(48.559,10.214)
PA8: CN2.10 U1.12 | length 23.6
  Top Layer w0.1: U1.12 43.994,9.967 44.211,9.75 44.211,9.48 v1(44.241,9.45)
  Bottom Layer w0.1: CN2.10 26.039,2.6 26.456,3.018 26.468,3.018 27.9,4.45 30.6,4.45 31.8,5.65 40.6,5.65 44.15,9.2 44.15,9.278 44.184,9.311 44.184,9.447 v1@44.15,9.481
PA9: CN2.11 U1.11 | length 24.8
  Top Layer w0.1: U1.11@43.594,11.175 43.594,9.875 43.694,9.775 43.694,9.519 v1(43.738,9.475)
  Bottom Layer w0.1: CN2.11@23.328,3.428 24.9,5 30.1,5 31,5.9 40.4,5.9 43.709,9.209 43.709,9.445 v1(43.738,9.475)
PA10: CN2.12 U1.10 | length 26.9
  Top Layer w0.1: U1.10 43.203,11.315 43.203,9.497 v1(43.213,9.487)
  Bottom Layer w0.1: CN2.12@20.774,3.474 22.75,5.45 29.5,5.45 30.2,6.15 40.15,6.15 43.187,9.187 43.187,9.462 v1(43.213,9.487)
PA11: CN2.13 U1.9 | length 29
  Top Layer w0.1: v1(42.794,9.765) U1.9@42.794,11.175
  Bottom Layer w0.1: CN2.13@17.945,3.5 18.35,3.5 20.75,5.9 29.15,5.9 29.65,6.4 39.7,6.4 42.757,9.457 42.757,9.728 v1(42.794,9.765)
PA12: CN2.14 U1.8 | length 31.7
  Top Layer w0.1: v1(42.302,9.546) 42.302,9.854 42.394,9.946 U1.8
  Bottom Layer w0.1: CN2.14@15.015,3.265 15.223,3.265 15.366,3.408 15.366,3.616 18.05,6.3 28.9,6.3 29.25,6.65 39.434,6.65 v1@42.204,9.419
PA13: CN2.15 U1.7 | length 33.4
  Top Layer w0.1: v1(41.756,9.467) 41.809,9.467 41.944,9.601 41.944,11.275 U1.7
  Bottom Layer w0.1: CN2.15@12.865,3.5 16.115,6.75 28.7,6.75 28.9,6.95 39.277,6.95 41.756,9.43 v1(41.756,9.467)
PA14: CN2.16 U1.6 | length 35.5
  Top Layer w0.1: v1(41.222,9.391) 41.222,9.448 41.544,9.77 41.544,11.275 U1.6
  Bottom Layer w0.1: CN2.16@10.325,3.5 13.975,7.15 28.45,7.15 28.55,7.25 39.163,7.25 41.222,9.31 v1(41.222,9.391)
PA15: CN2.17 U1.5 | length 37.4
  Top Layer w0.1: v1(40.728,9.315) 40.728,9.391 41.194,9.857 U1.5@41.194,11.175
  Bottom Layer w0.1: CN2.17@7.785,3.5 11.785,7.5 28.2,7.5 28.3,7.6 39.013,7.6 v1(40.728,9.315)
PB0: CN2.18 U1.4 | length 39.6
  Top Layer w0.1: v1(40.229,9.351) 40.229,9.36 40.794,9.924 U1.4
  Bottom Layer w0.1: CN2.18@5.245,3.5 9.645,7.9 38.792,7.9 40.229,9.337 v1(40.229,9.351)
PB1: CN1.18 U1.3 | length 51.8
  Top Layer w0.1: v1(39.58,9.275) 39.608,9.275 40.382,10.05 40.382,11.164 U1.3@40.394,11.175
  Bottom Layer w0.1: CN1.18@5.245,27.5 5.245,15.833 12.778,8.3 38.65,8.3 39.58,9.23 v1(39.58,9.275)
PB2: CN1.17 U1.2 | length 48.1
  Top Layer w0.1: v1(38.011,9.4) 38.02,9.4 38.22,9.6 39.45,9.6 39.994,10.144 U1.2
  Bottom Layer w0.1: CN1.17@7.785,27.5 7.785,16.815 15.95,8.65 37.3,8.65 v1@38.019,9.369
PB3: CN1.16 U1.1 | length 43.8
  Top Layer w0.1: v1(37.561,10.1) 37.561,10.17 38.698,11.307 39.575,11.307 U1.1
  Bottom Layer w0.1: CN1.16@10.325,27.5 10.325,17.475 18.75,9.05 36.643,9.05 37.504,9.911 37.504,9.961 37.538,9.996 v1@37.589,9.996
PB4: CN1.15 U1.48 | length 40.2
  Top Layer w0.1: v1(36.942,10.219) 36.942,10.274 37.198,10.529 38.569,11.9 U1.48
  Bottom Layer w0.1: CN1.15@12.865,27.5 12.865,18.085 21.5,9.45 36.211,9.45 36.942,10.181 v1(36.942,10.219)
PB5: CN1.14 U1.47 | length 37.1
  Top Layer w0.1: v1(36.589,10.573) 38.316,12.3 U1.47@38.868,12.3
  Bottom Layer w0.1: CN1.14@15.405,27.5 15.405,18.445 24,9.85 35.83,9.85 36.553,10.573 v1(36.589,10.573)
PB6: CN1.13 U1.46 | length 34.3
  Top Layer w0.1: v1(36.011,10.6) 36.092,10.6 36.19,10.697 36.208,10.697 38.211,12.7 U1.46@38.868,12.7
  Bottom Layer w0.1: CN1.13@17.945,27.5 17.945,18.455 26.1,10.3 35.7,10.3 ; 35.711,10.3 v1(36.011,10.6)
PB7: CN1.12 U1.45 | length 32.3
  Top Layer w0.1: v1(35.461,10.85) 35.511,10.85 35.792,11.131 36.242,11.131 38.211,13.1 U1.45@38.868,13.1
  Bottom Layer w0.1: CN1.12@20.555,28.019 20.95,27.624 20.95,17.4 27.565,10.785 35.2,10.785 ; 35.252,10.785 35.26,10.793 35.404,10.793 v1(35.461,10.85)
PB8: CN1.11 U1.44 | length 30.6
  Top Layer w0.1: v1(35.361,11.4) 36.111,11.4 38.211,13.5 U1.44@38.868,13.5
  Bottom Layer w0.1: CN1.11 23.15,28.275 23.15,16.862 28.762,11.25 35.15,11.25 ; 35.152,11.25 35.302,11.4 v1(35.361,11.4)
PB9: CN1.10 U1.43 | length 28.4
  Top Layer w0.1: v1(34.811,11.75) 36.061,11.75 38.211,13.9 U1.43@38.868,13.9
  Bottom Layer w0.1: CN1.10 25.8,28.165 25.8,15.8 29.9,11.7 v1@34.761,11.7 ; v1@34.8,11.7 v1@34.761,11.7 ; v1(34.811,11.75) v1@34.761,11.7
PB10: CN1.9 U1.42 | length 25.8
  Top Layer w0.1: v1(34.511,12.15) 36.091,12.15 38.241,14.3 U1.42@38.868,14.3
  Bottom Layer w0.1: CN1.9 28.105,15.615 31.571,12.15 v1@34.45,12.15
PB11: CN1.8 U1.41 | length 24
  Top Layer w0.1: v1(34.961,12.55) 35.011,12.5 36.041,12.5 38.241,14.7 U1.41@38.868,14.7
  Bottom Layer w0.1: CN1.8 30.645,14.292 32.397,12.54 34.951,12.54 v1(34.961,12.55)
PB12: CN1.6 SB1.1 | length 7.2
  Bottom Layer w0.1: CN1.6 35.967,28.159 36.44,28.159 36.596,28.002 36.648,28.002 40.373,24.277 SB1.1@40.373,23.418
PB13: CN1.5 SB2.1 | length 8.1
  Bottom Layer w0.1: CN1.5 39.865,26.8 41.216,26.8 43.821,24.196 43.821,23.479 SB2.1
PB14: CN1.4 U1.28 | length 16.3
  Top Layer w0.1: U1.28 42.844,16.925 42.844,17.252 42.991,17.4 42.991,19.183 43.941,20.133 43.941,21.28 44.461,21.8 45.761,21.8 46.111,22.15 v1@46.111,22.8
  Bottom Layer w0.1: CN1.4 40.927,28.279 41.822,28.279 46.1,24 v1(46.1,22.85)
PB15: CN1.3 U1.27 | length 16.1
  Top Layer w0.1: U1.27@43.194,17.025 43.194,19.102 44.141,20.05 44.141,21.18 44.561,21.6 46.933,21.6 47.172,21.839 47.172,22.591 47.3,22.719 v1(47.3,22.8)
  Bottom Layer w0.1: CN1.3 47.3,24.445 v1(47.3,22.8)
RSTN: C6.1 CN1.7 U1.38 | length 17.9
  Top Layer w0.1: v1@34.03,16.045 37.143,16.045 37.288,15.9 U1.38
  Bottom Layer w0.1: CN1.7 33.185,26.55 33.185,16.515 33.65,16.05 v1(33.95,16.05)
VDD: C3.2 C4.2 C7.2 C12.2 C16.2 C18.2 C21.2 CN1.1 U1.21 U1.23 U1.26 U1.36 U1.37 U1.39 | length 71.9
  Top Layer w0.2: U1.37@38.794,16.3 U1.37
  Top Layer w0.25: U1.23 44.95,15.9 46.493,17.443 C7.2@46.493,17.468 ; U1.21@44.571,15.1 45.01,15.1 C16.2@46.93,13.18
  Top Layer w0.29: U1.26@43.594,17.055 43.594,17.459 43.741,17.606 C21.2@43.741,18.4
  Top Layer w0.3: v1@35.637,16.831 35.668,16.8 36.593,16.8 36.788,16.605 37.136,16.605 C18.2@37.241,16.5 ; v1(36.091,18.4) 36.11,18.381 36.528,18.381 C3.2@37.085,18.38 ; v1@36.72,15.686 36.72,15.648 36.737,15.631 36.798,15.631 36.961,15.468 C12.2 ; C12.2@37.226,15.5 U1.39 ; C18.2@37.271,16.5 38.191,16.5 38.391,16.3 U1.37@38.794,16.3 ; C3.2@37.291,18.5 37.391,18.4 C4.2 ; C4.2@38.033,18.4 38.039,18.4 38.089,18.35 38.089,17.961 39.15,16.9 U1.36@39.5,16.9
  Top Layer w0.4: C21.2@43.747,18.423 43.747,19.057 44.521,19.831 v1(44.521,20.2)
  Top Layer w0.5: C7.2@46.574,17.504 48.291,19.221 v1(48.291,21.25) ; C16.2@46.982,13.282 46.989,13.282 v1(48.121,12.15)
  Bottom Layer w0.5: 35.591,18.4 v1(36.091,18.4) ; v1(36.691,15.65) 35.549,15.65 ; v1(44.521,20.2) 44.521,20.36 44.661,20.5 44.661,22.2 ; v1(48.121,12.15) 48.121,12.056 46.465,10.4 38.535,10.4 35.549,13.386 35.549,15.65 ; v1(48.291,21.25) 48.291,21.966 48.179,22.079 48.007,22.25 ; CN1.1 48.35,28.325 48.35,26.25 48.7,25.9 48.7,22.543 48.407,22.25 48.007,22.25 ; 35.549,15.65 35.549,20.658 37.141,22.25 44.661,22.25 48.007,22.25
  other v1: 35.591,16.85
pads on no net: U1.33

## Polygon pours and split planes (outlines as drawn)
GND on Bottom Layer "NONET_L-01_P-001" (solid, remove dead copper, pour order 0): 0,31 0,0 55.25,0 55.25,31
GND on Top Layer "NONET_L-01_P-001" (solid, remove dead copper, pour order 1): 0,31 0,0 55.25,0 55.25,31

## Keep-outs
Keep-Out Layer:
  lines w0.1: -0.05,0 ccw(c0,0) 0,-0.05 ; -0.05,0 ccw(c0,0) 0,-0.05 ; -0.05,0 -0.05,31 ; -0.05,31 cw(c0,31) 0,31.05 ; -0.05,31 cw(c0,31) 0,31.05 ; 0,-0.05 55.25,-0.05 ; 0,31.05 55.25,31.05 ; 55.25,-0.05 ccw(c55.25,0) 55.3,0 ; 55.25,-0.05 ccw(c55.25,0) 55.3,0 ; 55.25,31.05 cw(c55.25,31) 55.3,31 ; 55.25,31.05 cw(c55.25,31) 55.3,31 ; 55.3,0 55.3,31

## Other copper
Top Layer:
  pour cut-out: 46.365,15.5 ccw(c46.688,15.5) 46.688,15.177 ccw(c46.688,15.5) 47.011,15.5 ccw(c46.688,15.5) 46.688,15.823 ccw(c46.688,15.5)
  pour cut-out: 47.519,15.5 ccw(c47.842,15.5) 47.842,15.177 ccw(c47.842,15.5) 48.165,15.5 ccw(c47.842,15.5) 47.842,15.823 ccw(c47.842,15.5)
  pour cut-out: 48.118,15.01 48.15,15.01 48.15,15.99 48.118,15.99 47.903,15.775 47.842,15.775 47.842,15.225 47.903,15.225
  pour cut-out: 48.15,15.01 48.15,15.99 55.3,15.99 55.3,15.01
  pour cut-out: 44.45,15.225 44.45,15.775 46.687,15.775 46.687,15.225
  pour cut-out: 38.8,20.025 38.8,21.775 43.05,21.775 43.05,20.025
  pour cut-out: 40.294,17.1 40.494,17.1 40.494,16.55 40.294,16.55
  region net GND: 54.965,14.91 55.138,14.91 55.138,15 54.965,15
  region net GND: 54.865,14.91 55.038,14.91 55.038,15 54.865,15
  pour cut-out: 36.291,18.394 36.291,20.1 36.515,20.1 36.515,18.394
  pour cut-out: 36.366,20.1 38.916,20.1 38.916,19.95 36.366,19.95
  pour cut-out: 39.349,16.625 44.315,16.625 44.315,11.554 39.349,11.554
  text ".Layer_Name" at 9.099,-12.163 h3
  text ".GTL" at 50.793,-12.163 h3
Bottom Layer:
  pour cut-out: 30.5,4.473 30.5,4.95 27.931,4.95 27.931,4.474
  pour cut-out: 30.75,3.924 30.75,4.4 29.881,4.4 29.881,3.924
  pour cut-out: 31.076,3.976 32.025,4.925 30.938,6.012 29.989,5.064
  text ".GBL" at 39.59,-12.195 h3
  text ".Layer_Name" at 80.904,-12.195 h3

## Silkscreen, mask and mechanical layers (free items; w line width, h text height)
Top Overlay:
  lines w0.2: 39.114,17.75 39.562,17.75
  text "MB2172" at 11.819,20.569 h3 r270
  text ".Layer_Name" at 9.099,-12.163 h3
  text ".GTO" at 50.793,-12.163 h3
Bottom Overlay:
  text "RSTN" at 33.312,24.135 h0.64 r270
  text "GND" at 46.012,24.135 h0.64 r270
  text "VDD" at 48.552,24.135 h0.64 r270
  text "PA10" at 20.612,5.151 h0.64 r270
  text "TX" at 23.152,5.151 h0.64 r270
  text "RX" at 25.692,5.151 h0.64 r270
  text "SWCLK" at 35.852,5.151 h0.64 r270
  text "GND" at 48.552,5.151 h0.64 r270
  text "SWDIO" at 33.185,5.024 h0.64 r270
  text ".GBO" at 39.59,-12.195 h3
  text ".Layer_Name" at 80.904,-12.195 h3
Top Paste:
  text ".Layer_Name" at 9.099,-12.163 h3
  text ".GTP" at 50.793,-12.163 h3
Bottom Paste:
  text ".GBP" at 39.59,-12.195 h3
  text ".Layer_Name" at 80.904,-12.195 h3
Top Solder:
  text ".Layer_Name" at 9.099,-12.163 h3
  text ".GTS" at 50.793,-12.163 h3
Bottom Solder:
  text ".GBS" at 39.59,-12.195 h3
  text ".Layer_Name" at 80.904,-12.195 h3
Mechanical 1:
  lines w0.1: 55.25,0 55.25,31 ; 55.25,0 55.25,0 ; 55.25,0 0,0 0,31 55.25,31 ; 55.25,31 55.25,31 ; 55.25,31 55.25,31
Bottom Assembly:
  text ".Layer_Name" at 9.099,-12.163 h3
  text ".GM2" at 50.793,-12.163 h3
Mechanical 14:
  text ".Layer_Name" at 9.099,-12.163 h3
  text ".GM14" at 50.793,-12.163 h3
Mechanical 15:
  circle w0.2: c68.8,15.54 r0.61
  circle w0.2: c68.8,15.54 r1.205
  circle w0.2: c-4.1,41.628 r1.205
  circle w0.2: c-4.1,41.628 r0.61
  circle w0.2: c-4.1,-10.71 r1.205
  circle w0.2: c-4.1,-10.71 r0.61
  lines w0.2: -6.2,-10.71 -2,-10.71 ; -6.2,41.628 -2,41.628 ; -4.1,-12.8 -4.1,-8.61 ; -4.1,39.538 -4.1,43.728 ; 66.7,15.54 70.9,15.54 ; 68.8,13.45 68.8,17.64
  text ".GM15" at 39.59,-12.195 h3
  text ".Layer_Name" at 80.904,-12.195 h3
Drill Drawing:
  drawing of 159 lines, arcs and shapes, not listed
  text "Symbol" at 2.501,88.673 h1.83
  text "Count" at 15.35,88.673 h1.83
  text "Hole Size" at 30.586,88.673 h1.83
  text "Plated" at 58.264,88.673 h1.83
  text "Hole Type" at 71.113,88.673 h1.83
  text "Drill Layer Pair" at 89.752,88.673 h1.83
  text "Via/Pad" at 127.84,88.673 h1.83
  text "Pad Shape" at 142.822,88.673 h1.83
  text "Template" at 161.766,88.673 h1.83
  text "844" at 15.35,84.863 h1.52
  text "0.200mm (7.87mil)" at 30.586,84.863 h1.52
  text "PTH" at 58.264,84.863 h1.52
  text "Round" at 71.113,84.863 h1.52
  text "Top Layer - Bottom Layer" at 89.752,84.863 h1.52
  text "Via" at 127.84,84.863 h1.52
  text "Rounded" at 142.822,84.863 h1.52
  text "v40h20m0mx0" at 161.766,84.863 h1.52
  text "38" at 15.35,81.053 h1.52
  text "1.000mm (39.37mil)" at 30.586,81.053 h1.52
  text "PTH" at 58.264,81.053 h1.52
  text "Round" at 71.113,81.053 h1.52
  text "Top Layer - Bottom Layer" at 89.752,81.053 h1.52
  text "Pad" at 127.84,81.053 h1.52
  text "Rounded" at 142.822,81.053 h1.52
  text "(Mixed)" at 161.766,81.053 h1.52
  text "882 Total" at 15.35,77.243 h1.52
  text "PCB SPECIFICATIONS :" at 1.133,70.47 h3
  text "A.   MATERIAL :" at 1.133,66.47 h3
  text "FR-4" at 39.633,66.47 h3
  text "X  TG-170" at 56.133,66.47 h3
  text "TG-150" at 74.383,66.47 h3
  text "TG-140" at 90.383,66.47 h3
  text "B.   MATERIAL FAMILY :" at 1.133,63.47 h3
  text "N/A" at 39.633,63.47 h3
  text "C.   SOLDERMASK COLOR :" at 1.133,60.47 h3
  text "X   GREEN" at 39.633,60.47 h3
  text "BLUE" at 56.133,60.47 h3
  text "RED" at 74.383,60.47 h3
  text "BLACK" at 90.383,60.47 h3
  text "D.   SILKSCREEN COLOR :" at 1.133,57.47 h3
  text "X  WHITE" at 39.633,57.47 h3
  text "YELLOW" at 56.133,57.47 h3
  text "BLACK" at 74.383,57.47 h3
  text "E.   SURFACE FINISH :" at 1.133,54.47 h3
  text "X  ENIG" at 39.633,54.47 h3
  text "IMMERSION SILVER" at 56.133,54.47 h3
  text "IMMERSION TIN" at 90.383,54.47 h3
  text "HASL" at 39.633,51.47 h3
  text "HASL (PB-FREE)" at 56.133,51.47 h3
  text "GOLDEN FINGER" at 90.383,51.47 h3
  text "F.   IMPEDANCE CONTROL :" at 1.133,48.47 h3
  text "NO" at 39.633,48.47 h3
  text "X  YES  (SEE IMPEDANCE TABLE FOR DETAIL INFORMATION)" at 56.133,48.47 h3
  text "G.   THROUGH VIA :" at 1.133,45.47 h3
  text "PLUG THE VIAS WHICH ARE COVERED WITH SOLDERMASK ONE OR TWO SIDE." at 39.633,45.47 h3
  text "PLUG MATERIAL :" at 39.633,42.47 h3
  text "X  SOLDERMASK" at 65.133,42.47 h3
  text "NON-CONDUCTIVE EPOXY." at 90.383,42.47 h3
  text "H.   STACK-UP :" at 1.133,39.47 h3
  text "SEE LAYER STACK-UP SEQUENCE FOR OVERALL THICKNESS." at 39.633,39.47 h3
  text "Layer" at 78.601,28.906 h1.52
  text "Name" at 89.012,28.906 h1.52
  text "Material" at 112.628,28.906 h1.52
  text "Thickness" at 140.814,28.906 h1.52
  text "Constant" at 157.32,28.906 h1.52
  text "Top Overlay" at 89.012,25.858 h1.52
  text "Top Solder" at 89.012,22.81 h1.52
  text "Solder Resist" at 112.628,22.81 h1.52
  text "0.020mm" at 140.814,22.81 h1.52
  text "3.5" at 157.32,22.81 h1.52
  text "1" at 78.601,19.762 h1.52
  text "Top Layer" at 89.012,19.762 h1.52
  text "0.035mm" at 140.814,19.762 h1.52
  text "Dielectric 1" at 89.012,16.714 h1.52
  text "TU-768 (3 x 7628)" at 112.628,16.714 h1.52
  text "0.533mm" at 140.814,16.714 h1.52
  text "4.6" at 157.32,16.714 h1.52
  text "2" at 78.601,13.666 h1.52
  text "Bottom Layer" at 89.012,13.666 h1.52
  text "0.035mm" at 140.814,13.666 h1.52
  text "Bottom Solder" at 89.012,10.618 h1.52
  text "Solder Resist" at 112.628,10.618 h1.52
  text "0.020mm" at 140.814,10.618 h1.52
  text "3.5" at 157.32,10.618 h1.52
  text "Bottom Overlay" at 89.012,7.57 h1.52
  text "(mm)" at 113.45,-8.484 h3
  text "(mm)" at 123.85,-8.584 h3
  text ".Layer_Name" at 9.099,-12.163 h3
  text ".DRL" at 50.793,-12.163 h3
  text "57 ohm" at 141.15,-15.717 h3
  text "0.135" at 127.15,-15.767 h3
  text "+/- 10%" at 171.7,-15.828 h3
  text "TOP" at 92.85,-15.867 h3
  text "NA" at 157.7,-15.85 h3
  text "0.28" at 114.55,-15.967 h3
Mechanical 20:
  circle w0.254: c87.103,-18.884 r1.3
  region: 86.628,-11.647 71.101,-11.647 70.407,-13.423 69.196,-14.648 67.799,-12.788 67.799,-11.137 68.942,-9.74 70.378,-9.361 86.628,-9.361
  region: 72.625,-19.977 61.869,-19.977 62.862,-17.484 70.72,-17.484 71.169,-16.725 73.377,-19.273
  lines w0.254: 62.862,-17.484 71.654,-17.484 68.588,-13.946 cw(c70.392,-12.002) 70.632,-9.361 87.396,-9.361 86.634,-11.647 ; 66.176,-9.114 cw(c68.602,-10.085) 68.839,-7.482 ; 66.215,-9.082 61.869,-19.977 81.191,-19.977 ccw(c81.44,-17.242) 83.989,-18.262 ; 67.955,-13.017 73.377,-19.273 ; 68.209,-13.017 73.514,-19.138 ; 68.209,-12.763 73.514,-18.884 ; 68.307,-11.647 81.3,-11.647 ; 68.336,-12.636 73.641,-18.757 ; 68.463,-12.509 73.768,-18.63 ; 68.59,-12.382 73.895,-18.503 ; 68.717,-12.255 74.022,-18.376 ; 68.772,-10.302 74.077,-16.423 ; 68.84,-7.482 88.29,-7.482 83.99,-18.26 ; 68.844,-12.128 74.094,-18.186 ; 68.844,-11.874 74.149,-17.995 ; 68.844,-11.62 74.149,-17.741 ; 68.844,-10.731 74.149,-16.852 ; 68.971,-11.493 74.276,-17.614 ; 68.971,-11.112 74.276,-17.233 ; 70.343,-17.497 ccw(c70.448,-16.962) 70.745,-16.505 ; 71.429,-11.634 ccw(c71.403,-12.201) 71.073,-12.663 73.438,-15.392 cw(c71.634,-17.336) 72.366,-19.885 ; 77.71,-19.773 80.6,-11.393 ; 77.933,-19.723 80.802,-11.402 ; 78.06,-19.723 80.929,-11.402 ; 78.314,-19.723 81.183,-11.402 ; 78.568,-19.723 81.437,-11.402 ; 78.822,-19.723 81.691,-11.402 ; 79.076,-19.723 81.945,-11.402 ; 79.33,-19.723 82.199,-11.402 ; 79.584,-19.723 82.453,-11.402 ; 79.838,-19.723 82.707,-11.402 ; 80.046,-19.773 82.936,-11.393 ; 82.936,-11.647 86.628,-11.647 ; 85.96,-11.645 86.722,-9.359 ; 86.126,-11.647 86.888,-9.361 ; 86.38,-11.647 87.142,-9.361
  lines w0.3: 0.098,-23.863 90.098,-23.863 90.098,-3.863 0.098,-3.863 ; 0.098,-18.863 60.098,-18.863 ; 0.098,-13.863 60.098,-13.863 ; 0.098,-8.863 60.098,-8.863 ; 0.099,-23.863 0.099,-3.863 ; 40.098,-23.863 40.098,-8.863 ; 60.098,-23.863 60.098,-3.863 ; 77.71,-19.773 80.046,-19.773
  text "Project: '.Board_Name'" at 1.099,-7.079 h3
  text "Layer:" at 1.099,-12.163 h3
  text "Gerber:" at 41.087,-12.163 h3
  text "Variant: '.VariantName'" at 1.099,-17.163 h3
  text "Ref: '.Board_Reference'" at 41.214,-17.163 h3
  text "R" at 86.595,-19.646 h1.52
  text "Date: '.Board_Document_Date'" at 1.099,-22.163 h3
  text "Rev: '.Board_PCB_Revision'" at 41.157,-22.163 h3
Mechanical 21:
  circle w0.254: c3.281,-18.884 r1.3
  region: 17.759,-19.977 28.515,-19.977 27.522,-17.484 19.664,-17.484 19.216,-16.725 17.007,-19.273
  region: 3.756,-11.647 19.283,-11.647 19.978,-13.423 21.188,-14.648 22.585,-12.788 22.585,-11.137 21.442,-9.74 20.006,-9.361 3.756,-9.361
  lines w0.254: 3.242,-9.361 4.004,-11.647 ; 3.496,-9.361 4.258,-11.647 ; 3.662,-9.359 4.424,-11.645 ; 3.75,-11.647 2.988,-9.361 19.752,-9.361 cw(c19.992,-12.002) 21.796,-13.946 18.73,-17.484 27.522,-17.484 ; 3.756,-11.647 7.448,-11.647 ; 6.394,-18.26 2.095,-7.482 21.544,-7.482 ; 6.395,-18.262 ccw(c8.944,-17.242) 9.193,-19.977 28.515,-19.977 24.169,-9.082 ; 7.448,-11.393 10.338,-19.773 ; 7.677,-11.402 10.546,-19.723 ; 7.931,-11.402 10.8,-19.723 ; 8.185,-11.402 11.054,-19.723 ; 8.439,-11.402 11.308,-19.723 ; 8.693,-11.402 11.562,-19.723 ; 8.947,-11.402 11.816,-19.723 ; 9.084,-11.647 22.077,-11.647 ; 9.201,-11.402 12.07,-19.723 ; 9.455,-11.402 12.324,-19.723 ; 9.582,-11.402 12.451,-19.723 ; 9.784,-11.393 12.674,-19.773 ; 16.108,-17.614 21.413,-11.493 ; 16.108,-17.233 21.413,-11.112 ; 16.235,-17.995 21.54,-11.874 ; 16.235,-17.741 21.54,-11.62 ; 16.235,-16.852 21.54,-10.731 ; 16.29,-18.186 21.54,-12.128 ; 16.308,-16.423 21.613,-10.302 ; 16.362,-18.376 21.667,-12.255 ; 16.489,-18.503 21.794,-12.382 ; 16.616,-18.63 21.921,-12.509 ; 16.743,-18.757 22.048,-12.636 ; 16.87,-19.138 22.175,-13.017 ; 16.87,-18.884 22.175,-12.763 ; 17.007,-19.273 22.429,-13.017 ; 18.018,-19.885 cw(c18.75,-17.336) 16.946,-15.392 19.311,-12.663 ccw(c18.981,-12.201) 18.955,-11.634 ; 19.639,-16.505 ccw(c19.937,-16.962) 20.042,-17.497 ; 21.546,-7.482 cw(c21.782,-10.085) 24.208,-9.114
  lines w0.3: 10.338,-19.773 12.674,-19.773 ; 30.098,-23.863 30.098,-3.863 ; 30.098,-18.863 90.098,-18.863 ; 30.098,-13.863 90.098,-13.863 ; 30.098,-8.863 90.098,-8.863 ; 50.098,-23.863 50.098,-8.863 ; 0.098,-23.863 90.098,-23.863 90.098,-3.863 0.098,-3.863 0.098,-23.863
  text "Project: '.Board_Name'" at 88.904,-7.079 h3
  text "Gerber:" at 48.916,-12.163 h3
  text "Layer:" at 88.904,-12.163 h3
  text "Ref: '.Board_Reference'" at 48.916,-17.163 h3
  text "Variant: '.VariantName'" at 88.904,-17.163 h3
  text "R" at 3.789,-19.646 h1.52
  text "Rev: '.Board_PCB_Revision'" at 48.973,-22.163 h3
  text "Date: '.Board_Document_Date'" at 88.904,-22.163 h3

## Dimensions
0,31 to 55.25,31 on Mechanical 16
0,31 to 0,0 on Mechanical 16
